// Mitsubishi GX Works2 project: PID模拟恒定水位   PLC: FX3U/FX3UC

PROGRAM MAIN
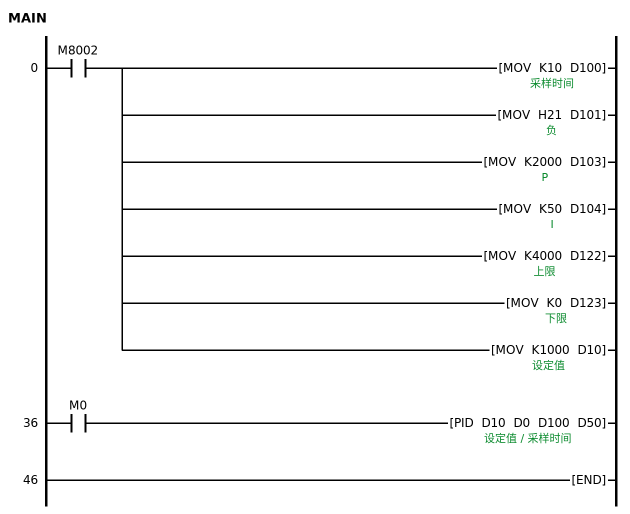
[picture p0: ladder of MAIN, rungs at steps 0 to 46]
0     LD      M8002
      MOV     K10 D100  ; 采样时间
      MOV     H21 D101  ; 负
      MOV     K2000 D103  ; P
      MOV     K50 D104  ; I
      MOV     K4000 D122  ; 上限
      MOV     K0 D123  ; 下限
      MOV     K1000 D10  ; 设定值
36    LD      M0
      PID     D10 D0 D100 D50
46    END
END_PROGRAM
